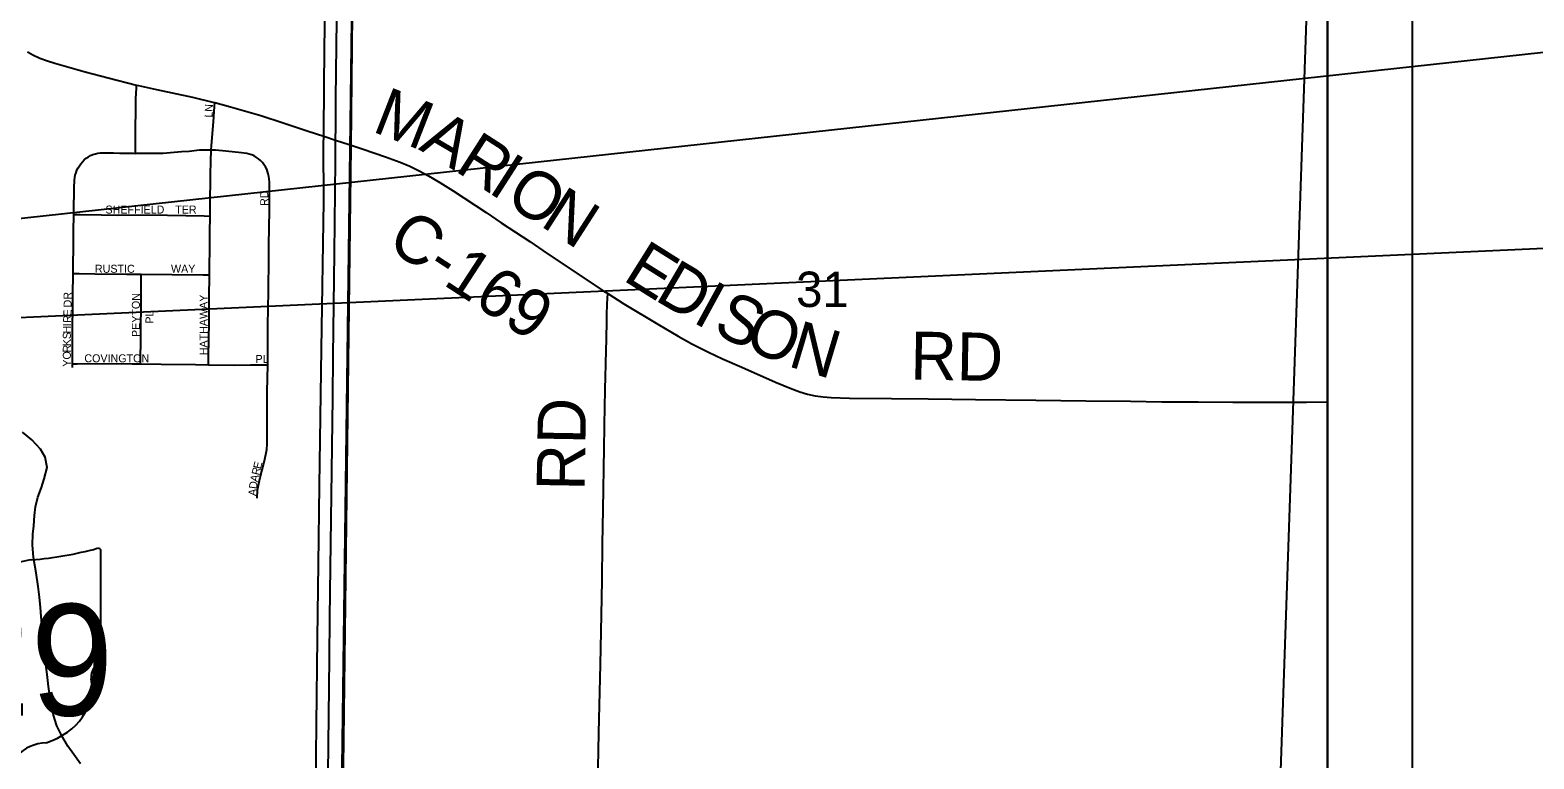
# Model space of a CAD drawing. Extents: x -9.1 to 34, y -3.1 to 22.
# Drawn here: x 7.865 to 9.644, y 17.82 to 18.681 of the extents above; entities that cross this region are included whole.
import ezdxf

# ---------------------------------------------------------------- set-up
doc = ezdxf.new("R2010")
doc.units = 0
for name, color, linetype in [('GM_X_County_Road', 7, 'Continuous'), ('GM_X_County_Road_Text', 7, 'Continuous'), ('GM_X_Minor_River', 7, 'Continuous'), ('GM_X_Section', 7, 'Continuous'), ('GM_X_Section_Text', 7, 'Continuous'), ('GM_X_State_Shield', 7, 'Continuous'), ('GM_X_Township', 7, 'Continuous'), ('GM_X_Township_Road', 7, 'Continuous'), ('GM_X_Township_Road_Text', 7, 'Continuous'), ('GM_X_Township_Subdivision', 7, 'Continuous'), ('GM_X_Township_Subdivision_Text', 7, 'Continuous'), ('GM_X_US_Route', 7, 'Continuous'), ('SH_Data', 7, 'Continuous'), ('SH_Text', 7, 'Continuous')]:
    doc.layers.add(name, color=color, linetype=linetype)

msp = doc.modelspace()

# ---------------------------------------------------------------- linework, layer by layer
at = {"layer": 'GM_X_County_Road'}
for points in [[(7.8619, 18.6557), (7.8626, 18.6552), (7.8681, 18.6522), (7.8766, 18.6483), (7.8854, 18.645), (7.8943, 18.6421), (7.9302, 18.6321), (7.9572, 18.6249), (7.991, 18.6164)], [(7.991, 18.6164), (7.9934, 18.6158), (8.0146, 18.611), (8.0572, 18.602), (8.0813, 18.5963), (8.0834, 18.5957)], [(8.0834, 18.5957), (8.1023, 18.5907), (8.138, 18.5802), (8.1646, 18.5716), (8.1941, 18.5618), (8.2124, 18.5558), (8.2265, 18.5511), (8.2426, 18.5459)], [(8.2426, 18.5459), (8.259, 18.5405), (8.2855, 18.5316), (8.3029, 18.5252), (8.3143, 18.5204), (8.3255, 18.515), (8.3364, 18.5092), (8.3497, 18.5013), (8.3654, 18.4912), (8.4044, 18.4656), (8.4225, 18.4536), (8.4561, 18.4312), (8.4767, 18.4173), (8.544, 18.3727), (8.5485, 18.3699)], [(8.5485, 18.3699), (8.5676, 18.3577), (8.6076, 18.3336), (8.6317, 18.3195), (8.6481, 18.3105), (8.6675, 18.3006), (8.6844, 18.2927), (8.7071, 18.2826), (8.7469, 18.2652), (8.7642, 18.258), (8.7759, 18.2536), (8.7848, 18.2509), (8.794, 18.2489), (8.8033, 18.2477), (8.8127, 18.247), (8.8344, 18.2463), (8.8842, 18.2458), (8.9276, 18.2453), (8.9836, 18.2446), (9.055, 18.2437), (9.114, 18.2429), (9.1669, 18.2425), (9.2041, 18.2418), (9.2468, 18.2416), (9.288, 18.2414), (9.3253, 18.2412), (9.375, 18.2415), (9.4, 18.2417)]]:
    msp.add_lwpolyline(points, dxfattribs=at)
at = {"layer": 'GM_X_Minor_River'}
for points in [[(7.867, 18.1967), (7.8561, 18.2058)], [(7.9247, 17.8136), (7.9168, 17.8246), (7.9097, 17.8345), (7.9021, 17.8478), (7.8965, 17.8585), (7.8924, 17.8725), (7.8901, 17.8843), (7.8883, 17.8945), (7.8868, 17.9051), (7.8853, 17.9195), (7.8831, 17.9339), (7.8816, 17.9442), (7.8813, 17.9559), (7.8798, 17.9696), (7.878, 17.9878), (7.8773, 17.9984), (7.8762, 18.0109), (7.8747, 18.0234), (7.8721, 18.0397), (7.8692, 18.0576), (7.8677, 18.0727), (7.8681, 18.0852), (7.8693, 18.0951), (7.8701, 18.1072), (7.8713, 18.1175), (7.874, 18.1292), (7.8786, 18.1406), (7.8816, 18.1508), (7.8851, 18.164), (7.8829, 18.1762), (7.8772, 18.186), (7.867, 18.1967)]]:
    msp.add_lwpolyline(points, dxfattribs=at)
at = {"layer": 'GM_X_Section'}
msp.add_line((9.4, 17.736), (9.4, 18.7507), dxfattribs=at)
for points in [[(7.2285, 18.7534), (8.2465, 18.7547), (8.2334, 17.7485), (7.2227, 17.7567)], [(9.3766, 18.7507), (9.3419, 17.736), (8.2334, 17.7485), (8.2465, 18.7547)]]:
    msp.add_lwpolyline(points, close=True, dxfattribs=at)
msp.add_lwpolyline([(9.4, 18.7507), (9.3766, 18.7507), (9.3419, 17.736), (9.4, 17.736)], dxfattribs=at)
at = {"layer": 'GM_X_State_Shield'}
for p, q in [((7.9487, 17.9605), (7.9487, 18.0652)), ((7.9487, 17.9606), (7.9487, 17.9605))]:
    msp.add_line(p, q, dxfattribs=at)
for centre, major_axis, start_param, end_param in [((7.8313, 18.3331), (0.3495, 0), 4.814394, 5.042369), ((7.9451, 18.0657), (0.00367, 0), 6.141152, 7.989035), ((7.8759, 17.9991), (0.0703, 0), 1.699011, 2.107814), ((7.9479, 17.9528), (0.00568, 0), 1.883978, 3.671073), ((7.9448, 17.9601), (0.00393, 0), 5.05454, 6.418171), ((7.9118, 17.9396), (0.0341, 0), 5.934695, 6.695948), ((7.9619, 17.9167), (0.0248, 0), 2.387724, 3.262537), ((7.8509, 17.9034), (0.0874, 0), 5.101752, 6.440018), ((7.8878, 17.8005), (0.0479, 0), 1.647645, 2.488434)]:
    msp.add_ellipse(centre, major_axis=major_axis, ratio=0.8, start_param=start_param, end_param=end_param, dxfattribs=at)
at = {"layer": 'GM_X_Township'}
for points in [[(8.2717, 20.9), (8.2689, 20.7443), (8.2697, 20.6456), (8.2583, 19.8928), (8.2535, 19.4485), (8.2445, 18.5434), (8.2345, 17.7477), (8.5348, 17.7425), (9.3398, 17.7284), (9.4, 17.7292)], [(9.4, 17.7292), (9.4, 20.9), (8.2717, 20.9)]]:
    msp.add_lwpolyline(points, dxfattribs=at)
at = {"layer": 'GM_X_Township_Road'}
msp.add_lwpolyline([(8.536, 17.7468), (8.5379, 17.8502), (8.5398, 17.931), (8.5409, 17.99), (8.5418, 18.0304), (8.5424, 18.0739), (8.5429, 18.1143), (8.5442, 18.187), (8.5451, 18.2375), (8.5452, 18.2542), (8.5457, 18.2741), (8.546, 18.2835), (8.5462, 18.292), (8.5464, 18.2978), (8.5466, 18.3052), (8.5468, 18.3128), (8.5469, 18.321), (8.5472, 18.3325), (8.5474, 18.3486), (8.5476, 18.3534), (8.5477, 18.3572), (8.5481, 18.3641), (8.5485, 18.3699)], dxfattribs=at)
at = {"layer": 'GM_X_Township_Subdivision'}
for points in [[(7.9897, 18.5356), (7.9897, 18.5408), (7.9899, 18.5441), (7.9899, 18.5528), (7.9899, 18.5655), (7.9899, 18.5729), (7.99, 18.5788), (7.99, 18.5914), (7.9902, 18.6003), (7.9908, 18.6125), (7.991, 18.6164)], [(8.0793, 18.5393), (8.0796, 18.545), (8.0818, 18.5729), (8.0831, 18.5912), (8.0834, 18.5957)], [(7.9166, 18.4634), (7.9166, 18.4669), (7.9171, 18.4948), (7.9175, 18.504), (7.9179, 18.507), (7.9185, 18.51), (7.9194, 18.5129), (7.9204, 18.5157), (7.9217, 18.5184), (7.9233, 18.521), (7.925, 18.5234), (7.927, 18.5257), (7.9291, 18.5279), (7.9315, 18.5298), (7.934, 18.5315), (7.9366, 18.533), (7.9393, 18.5342), (7.9422, 18.5351), (7.9451, 18.5357), (7.9481, 18.5361), (7.9512, 18.5362), (7.9635, 18.5361), (7.9712, 18.5358), (7.9756, 18.5358), (7.9815, 18.5357), (7.9873, 18.5357), (7.9897, 18.5356)], [(8.0793, 18.5393), (8.0749, 18.5395), (8.0656, 18.5392), (8.0533, 18.5378), (8.044, 18.5373), (8.0223, 18.5356), (8.0099, 18.5353), (7.9975, 18.5355), (7.9897, 18.5356)], [(8.0779, 18.4615), (8.078, 18.4733), (8.0783, 18.5107), (8.0787, 18.5263), (8.0793, 18.5393)], [(8.1462, 18.2857), (8.1462, 18.288), (8.1464, 18.3066), (8.1463, 18.3315), (8.1466, 18.3531), (8.1469, 18.3717), (8.1473, 18.412), (8.1475, 18.4276), (8.1482, 18.4679), (8.1483, 18.4896), (8.1481, 18.502), (8.1475, 18.5082), (8.1468, 18.5113), (8.146, 18.5142), (8.1449, 18.5171), (8.1434, 18.5198), (8.1417, 18.5224), (8.1398, 18.5248), (8.1376, 18.5271), (8.1353, 18.5291), (8.1328, 18.5309), (8.1301, 18.5325), (8.1272, 18.5337), (8.1243, 18.5348), (8.1213, 18.5355), (8.1152, 18.5364), (8.0966, 18.5382), (8.0842, 18.5392), (8.0793, 18.5393)], [(7.9159, 18.3935), (7.916, 18.4026), (7.9162, 18.4258), (7.9164, 18.4431), (7.9166, 18.4634)], [(7.9166, 18.4634), (7.9244, 18.4633), (7.9494, 18.4629), (7.9681, 18.4626), (7.9962, 18.4629), (8.0274, 18.4625), (8.0711, 18.4617), (8.0779, 18.4615)], [(8.0772, 18.3919), (8.0774, 18.3983), (8.0774, 18.4077), (8.0775, 18.4171), (8.0778, 18.442), (8.0779, 18.4615)], [(7.9151, 18.2868), (7.9151, 18.2932), (7.9151, 18.3078), (7.9151, 18.3204), (7.9153, 18.3319), (7.9155, 18.3507), (7.9156, 18.3676), (7.9157, 18.376), (7.9158, 18.3854), (7.9159, 18.3935)], [(7.9159, 18.3935), (7.923, 18.3934), (7.9417, 18.393), (7.9791, 18.3927), (7.9964, 18.3926)], [(7.9955, 18.2867), (7.9956, 18.2941), (7.9959, 18.3127), (7.9965, 18.3713), (7.9964, 18.3867), (7.9964, 18.3926)], [(7.9964, 18.3926), (8.0696, 18.3919), (8.0772, 18.3919)], [(8.076, 18.2857), (8.076, 18.2922), (8.0761, 18.2953), (8.0768, 18.3359), (8.0767, 18.3453), (8.0768, 18.3515), (8.0768, 18.3671), (8.0772, 18.3897), (8.0772, 18.3919)], [(7.9151, 18.2868), (7.9205, 18.2868), (7.936, 18.287), (7.9858, 18.2868), (7.9955, 18.2867)], [(7.9151, 18.2823), (7.9151, 18.2868)], [(7.9955, 18.2867), (8.0201, 18.2862), (8.0605, 18.2859), (8.076, 18.2857)], [(8.076, 18.2857), (8.1072, 18.2853), (8.1258, 18.2855), (8.1351, 18.2856), (8.1413, 18.2857), (8.1462, 18.2857)], [(8.1337, 18.128), (8.1342, 18.1372), (8.1351, 18.1433), (8.1371, 18.1524), (8.142, 18.1704), (8.144, 18.1795), (8.1449, 18.1856), (8.1453, 18.1918), (8.1456, 18.229), (8.1456, 18.2538), (8.1462, 18.2857)]]:
    msp.add_lwpolyline(points, dxfattribs=at)
at = {"layer": 'GM_X_US_Route'}
for points in [[(8.2176, 17.8023), (8.2192, 17.939), (8.2198, 17.9855), (8.2201, 18.0166), (8.223, 18.2465), (8.2235, 18.2962), (8.2251, 18.4174), (8.2262, 18.5262), (8.2265, 18.5511), (8.2266, 18.5664), (8.2268, 18.6005), (8.2271, 18.6316), (8.2282, 18.7248), (8.2315, 18.9764), (8.2308, 19.0168), (8.2288, 19.0571), (8.2253, 19.0973), (8.2222, 19.1222)], [(8.2028, 17.7513), (8.204, 17.8603), (8.2052, 17.9628), (8.2063, 18.0498), (8.2076, 18.143), (8.2097, 18.3046), (8.2124, 18.4786), (8.2123, 18.547), (8.2124, 18.5558), (8.2128, 18.6185), (8.2154, 18.8328)]]:
    msp.add_lwpolyline(points, dxfattribs=at)
at = {"layer": 'SH_Data'}
for p, q in [((9.5, 21), (9.5, 14)), ((9.4, 20.9), (9.4, 14.1))]:
    msp.add_line(p, q, dxfattribs=at)
at = {"layer": 'SH_Text'}
msp.add_lwpolyline([(9.7171, 18.426), (6.0037, 18.2573), (9.7171, 18.662)], close=True, dxfattribs=at)

# ---------------------------------------------------------------- texts
at = {"layer": 'GM_X_County_Road_Text'}
for s, height, rotation, p in [('M', 0.0568, 338.7087, (8.2682, 18.562)), ('A', 0.0568, 329.5548, (8.3236, 18.5407)), ('R', 0.0568, 327.2842, (8.3661, 18.5157)), ('I', 0.0568, 327.2474, (8.4054, 18.4904)), ('O', 0.0568, 327.2533, (8.425, 18.4778)), ('N', 0.0568, 327.2505, (8.4671, 18.4508)), ('C-169', 0.05682, 326.9031, (8.2851, 18.425)), ('E', 0.0568, 327.8815, (8.5648, 18.3866)), ('D', 0.0568, 329.637, (8.6024, 18.363)), ('I', 0.0568, 331.3606, (8.6472, 18.3368)), ('S', 0.0568, 334.8844, (8.6711, 18.3239)), ('O', 0.0568, 336.3417, (8.7072, 18.3069)), ('N', 0.0568, 343.3341, (8.7601, 18.2843)), ('RD', 0.05682, 359.0181, (8.9061, 18.2682))]:
    msp.add_text(s, height=height, rotation=rotation, dxfattribs=at).set_placement(p)
at = {"layer": 'GM_X_Section_Text'}
msp.add_text('31', height=0.04186, rotation=0, dxfattribs=at).set_placement((8.7713, 18.3539))
at = {"layer": 'GM_X_State_Shield'}
msp.add_text('529', height=0.13184, dxfattribs=at).set_placement((7.6695, 17.8708))
at = {"layer": 'GM_X_Township_Road_Text'}
msp.add_text('RD', height=0.05682, rotation=89.0128, dxfattribs=at).set_placement((8.521, 18.1363))
at = {"layer": 'GM_X_Township_Subdivision_Text'}
for s, rotation, p in [('L', 86.5822, (8.0807, 18.5777)), ('N', 87.2946, (8.0811, 18.5845)), ('RD', 90, (8.1467, 18.4734)), ('SHEFFIELD', 0, (7.9542, 18.4644)), ('TER', 0, (8.0367, 18.4644)), ('RUSTIC', 0, (7.9417, 18.3944)), ('WAY', 0, (8.0317, 18.3944)), ('DR', 90, (7.9141, 18.3534)), ('PEYTON', 90, (7.9949, 18.3184)), ('HATHAWAY', 90, (8.0749, 18.2968)), ('E', 87.4036, (7.9137, 18.3425)), ('PL', 90, (8.011, 18.3343)), ('I', 88.4696, (7.9133, 18.3309)), ('H', 89.7377, (7.9132, 18.3226)), ('R', 87.4978, (7.9134, 18.335)), ('S', 89.9821, (7.9132, 18.3159)), ('K', 89.9703, (7.9132, 18.3076)), ('R', 89.9757, (7.9132, 18.3001)), ('O', 89.9928, (7.9132, 18.2918)), ('Y', 89.9781, (7.9132, 18.2834)), ('COVINGTON', 0, (7.9292, 18.2885)), ('PL', 0, (8.1317, 18.2877)), ('E', 75.9781, (8.1379, 18.1617)), ('A', 77.0611, (8.1342, 18.1464)), ('R', 75.9696, (8.136, 18.1544)), ('A', 85.3834, (8.1325, 18.1302)), ('D', 82.6581, (8.1332, 18.1383))]:
    msp.add_text(s, height=0.00947, rotation=rotation, dxfattribs=at).set_placement(p)

doc.saveas('drawing.dxf')
